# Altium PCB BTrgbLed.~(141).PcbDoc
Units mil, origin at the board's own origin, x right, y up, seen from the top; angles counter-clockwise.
Board outline 3886.28 x 3884.79 mil, 2 copper layers (Top Layer, Bottom Layer); 15 components, 12 nets, 66 pads, 7 vias.
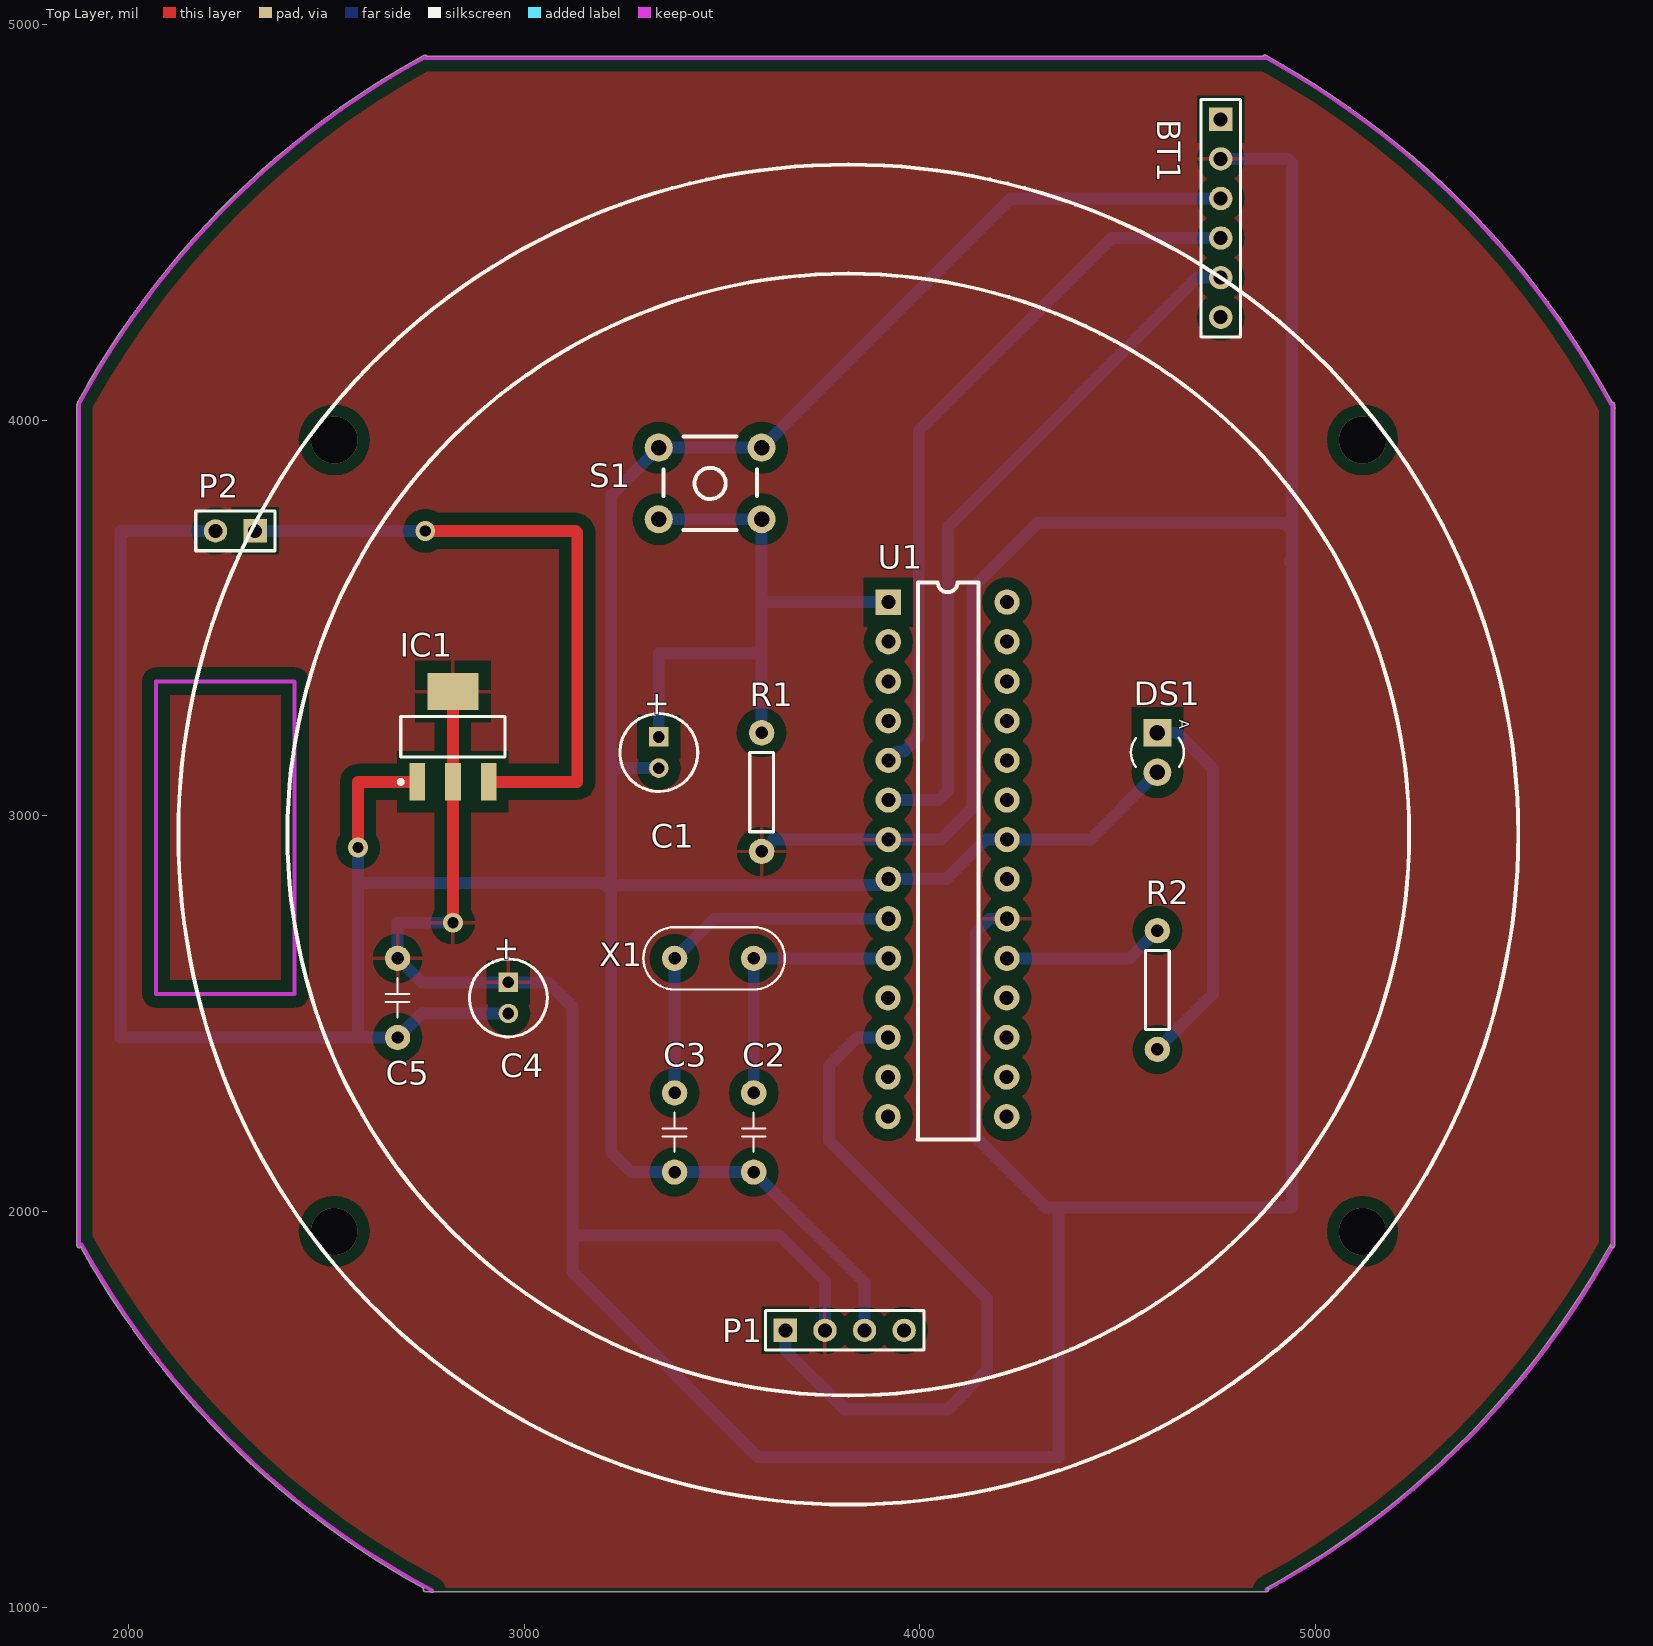
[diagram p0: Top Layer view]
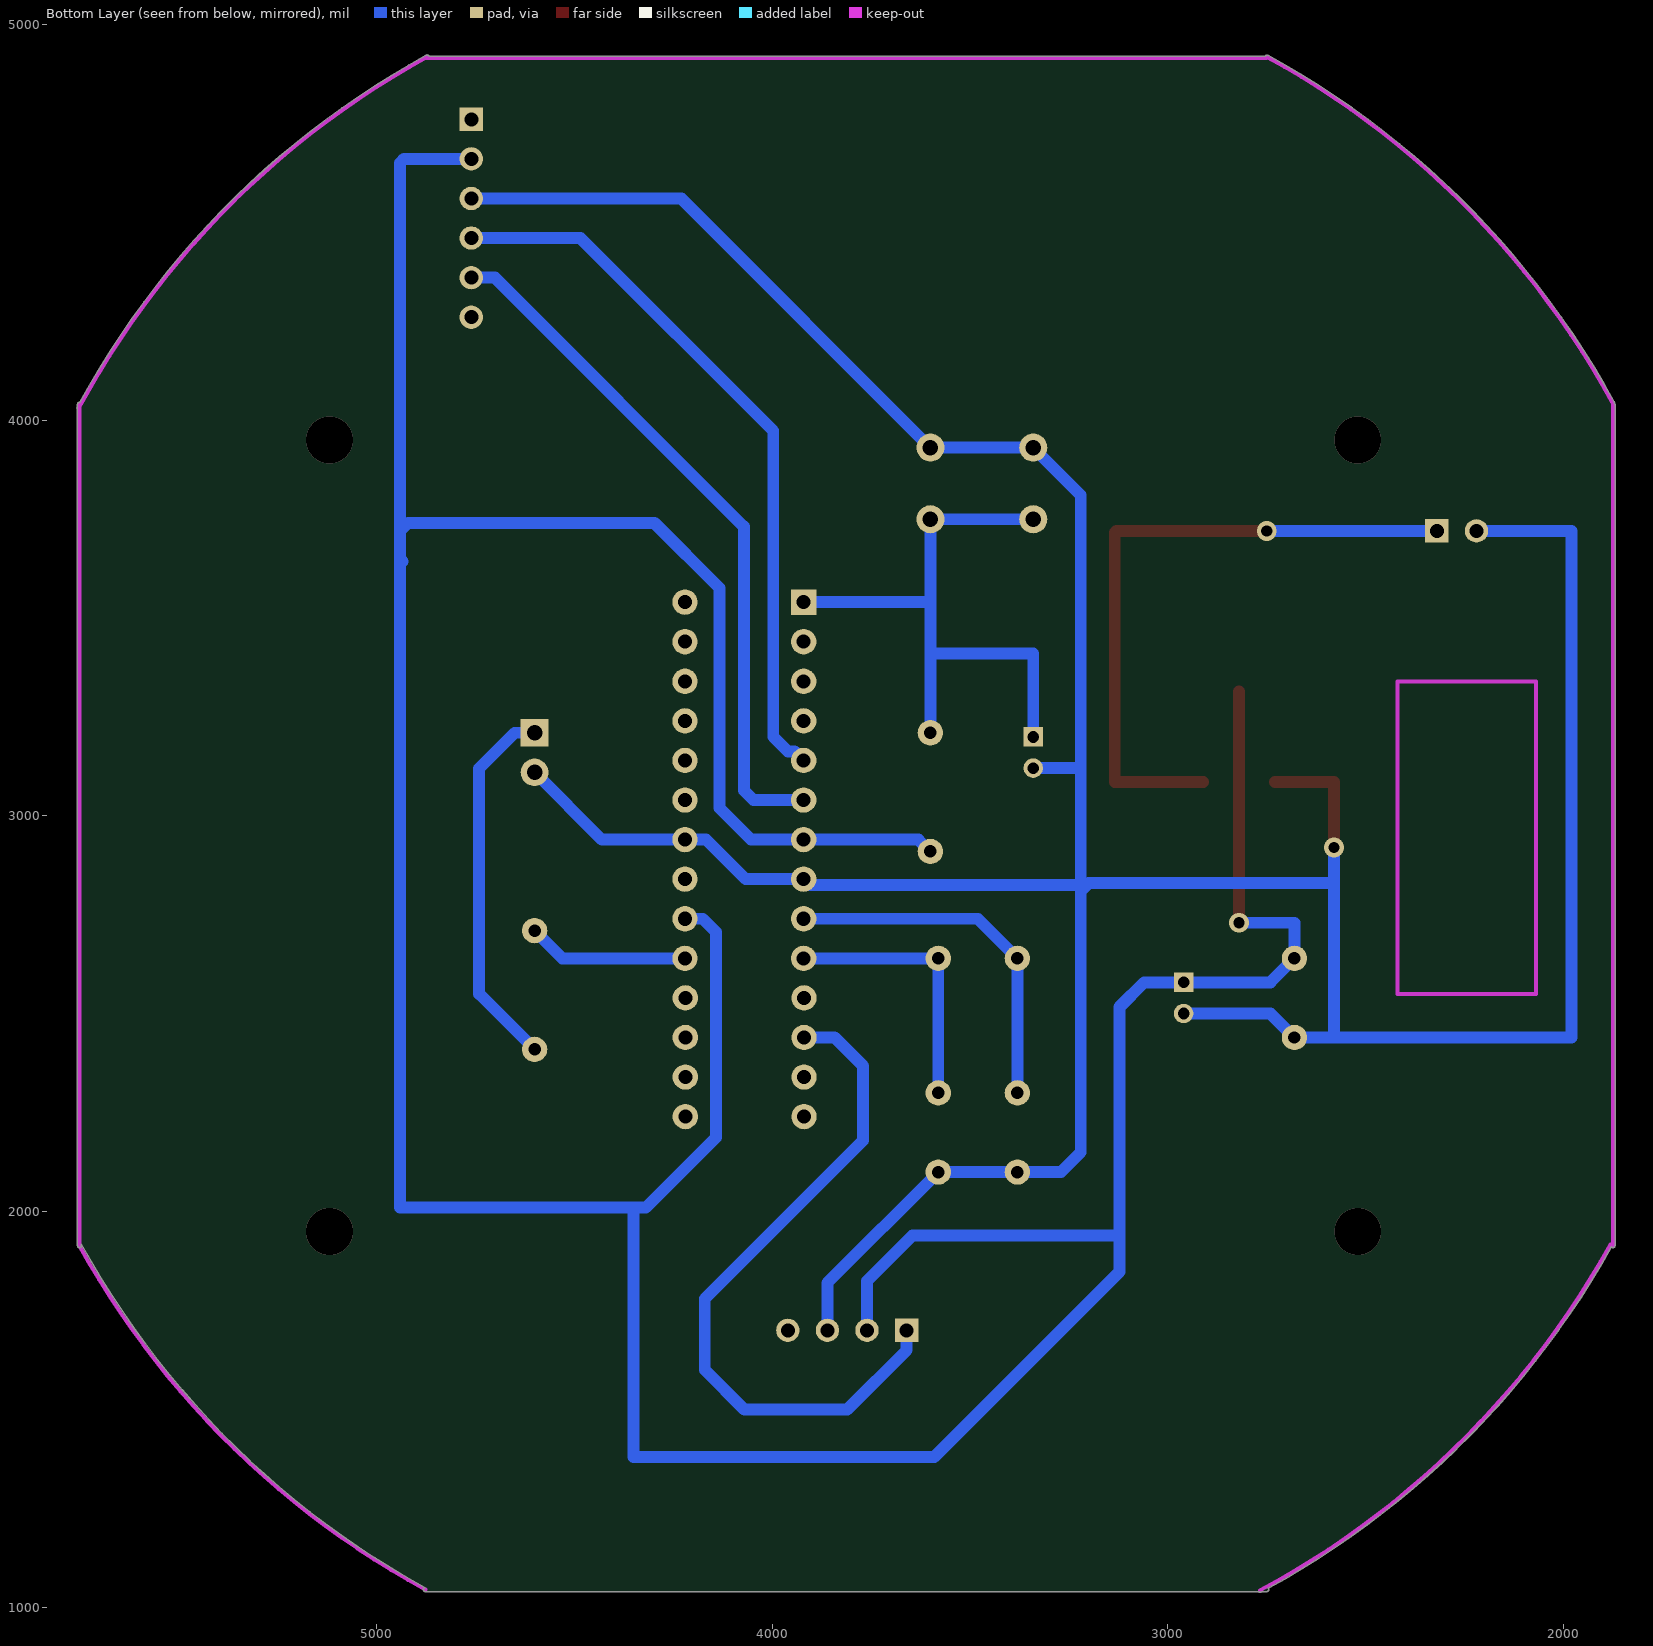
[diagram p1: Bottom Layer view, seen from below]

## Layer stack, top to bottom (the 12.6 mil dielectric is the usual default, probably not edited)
Top Layer: signal copper 1.4
Dielectric: dielectric 12.6, FR-4, Dk 4.8
Bottom Layer: signal copper 1.4

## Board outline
2750,1039.98 2761.53,1039.98 ccw(c3810.28,2985) 2764.5,1038.38 ccw(c2766.88,1042.8) 2771.03,1039.98 4875.98,1039.98 ccw(c4875.98,1045) 4881,1045 ccw(c4875.98,1045) 4877.16,1049.88 ccw(c3810.28,2985) 5744.74,1916.92 ccw(c5740.35,1919.34) 5744.98,1917.43 5744.98,1914.02 ccw(c5750,1914.02) 5755.02,1914.02 5755.02,4027.36 ccw(c5751.25,4030.67) 5756.26,4030.67 ccw(c5751.25,4030.67) 5755.66,4033.05 ccw(c3810.28,2985) 5755.02,4034.26 5755.02,4040 ccw(c5750,4040) 5749.21,4044.95 ccw(c3810.28,2985) 4873.82,4921.96 ccw(c4871.41,4917.56) 4867.03,4920.02 2752.96,4920.02 ccw(c2748.72,4917.33) 2746.3,4921.73 ccw(c3810.28,2985) 1872.41,4046.9 ccw(c1876.81,4044.49) 1871.83,4043.89 ccw(c1875,4040) 1869.98,4040 1869.98,1914.02 ccw(c1875,1914.02) 1879.06,1911.07 ccw(c3810.28,2985) 2746.23,1048.31 ccw(c2750,1045)

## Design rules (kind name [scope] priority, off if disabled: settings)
Clearance 舖銅安全間距 [All] p1: gap=30
Clearance [All] p2: gap=10
PolygonConnect [All] p1: connectstyle=Relief reliefconductorwidth=10 reliefentries=4 polygonreliefangle="90 Angle"
RoutingLayers [All] p1: top layer_v5=FALSE bottom layer_v5=TRUE
RoutingVias [All] p1: holewidth=28 width=50 viastyle="Through Hole" minholewidth=28 minwidth=50 maxholewidth=28 maxwidth=50
SilkscreenOverComponentPads [All] p1: minsilkscreentomaskgap=10
SolderMaskExpansion [All] p1: expansion=4
Width [All] p1: maxlimit=40 minlimit=20 preferedwidth=30
26 further rules are at their usual default settings.

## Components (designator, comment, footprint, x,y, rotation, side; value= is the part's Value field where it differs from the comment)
BT1 "Bluetooth" Bluetooth 4760,4760 r270 top
C1 "47uF" CAPPR2-5x6.8 3340,3160 r270 top
C2 "22pF" C200 3580,2200 r180 top
C3 "22pF" C200 3380,2200 r180 top
C4 "47uF" CAPPR2-5x6.8 2960,2540 r270 top
C5 "100pF" C200 2680,2540 r180 top
DS1 "TX-LED" LED-3mm_G 4600,3160 r270 top
IC1 "AM1117-5V" SOT-223 2820,3200 r90 top
P1 "環形LED燈" HDR1X4 3660,1700 r0 top
P2 "12V" HDR1X2 2320,3720 r180 top
R1 "10k" AXIAL-0.3 3600,3060 r90 top
R2 "220" AXIAL-0.3 4600,2560 r90 top
S1 "SW-PB" TACK6 3469.86,3840 r0 top
U1 "ATmega328" DIP-28 3920,3540 r270 top
X1 "16MHz" XTAL4-8 3480,2640 r0 top

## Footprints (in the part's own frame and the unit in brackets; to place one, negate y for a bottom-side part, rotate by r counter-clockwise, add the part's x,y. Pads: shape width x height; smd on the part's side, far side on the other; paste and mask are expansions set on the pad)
AXIAL-0.3 [mil] "0.3\" Resistor; 2 Leads"
  round 64 hole 31.5: 1(-150,0) 2(150,0)
  silkscreen extent -100,-30 100,30, body extent -161,-39 165,39, height 86
Bluetooth [mm]
  rect 1.5x1.5 hole 0.9: 1(0,0)
  round 1.5 hole 0.9: 2(2.54,0) 3(5.08,0) 4(7.62,0) 5(10.16,0) 6(12.7,0)
  silkscreen extent -1.27,-1.27 13.97,1.27, body extent -1.25,-1.3 13.97,1.28, height 11
C200 [mil] "塑膠電容器"
  round 64 hole 31.5: 1(0,100) 2(0,-100)
  silkscreen extent -30,-50 30,50, body extent -41,-136 39,135, height 354
CAPPR2-5x6.8 [mm] "Capacitor, Electrolytic, Radial; Body 5 x 6.8 mm (Dia.xH typ); Pin Spacing 2 mm (typ)"
  rect 1.25x1.25 hole 0.75: 1(-1,0)
  round 1.25 hole 0.75: 2(1,0)
  silkscreen extent -2.5,-2.5 2.5,2.5
DIP-28 [mil]
  rect 64x64 hole 35.43: 1(0,0)
  round 64 hole 35.43: 2(100,0) 3(200,0) 4(300,0) 5(400,0) 6(500,0) 7(600,0) 8(700,0) 9(800,0) 10(900,0) 11(1000,-0.79) 12(1100,-0.79) 13(1200,-0.79) 14(1300,-0.79) 15(1300,299.21) 16(1200,299.21) 17(1100,299.21) 18(1000,299.21) 19(900,300) 20(800,300) 21(700,300) 22(600,300) 23(500,300) 24(400,300) 25(300,300) 26(200,300) 27(100,300) 28(0,300)
  silkscreen extent -50,74 1358,228, body extent -53,-5 1358,304, height 209
HDR1X2 [mm] "Connector; Header; 2 Position"
  rect 1.5x1.5 hole 0.9: 1(0,0)
  round 1.5 hole 0.9: 2(2.54,0)
  silkscreen extent -1.27,-1.27 3.81,1.27
HDR1X4 [mm] "Connector; Header; 4 Position"
  rect 1.5x1.5 hole 0.9: 1(0,0)
  round 1.5 hole 0.9: 2(2.54,0) 3(5.08,0) 4(7.62,0)
  silkscreen extent -1.27,-1.27 8.89,1.27
LED-3mm_G [mil] "3mm LED_Green"
  rect 70x70 hole 39: 1(-50,0)
  round 70 hole 39: 2(50,0)
  silkscreen extent -38,-67 35,67, body extent -66,-68 67,66, height 181
SOT-223 [mm] "SOT223, 4-Leads, Body 6.7x7.3mm (max), Pitch 2.30mm, IPC Medium Density"
  rect 2.4x1 smd: 1(-2.9,2.3) 2(-2.9,0) 3(-2.9,-2.3)
  rect 2.4x3.3 smd: 2(2.9,0)
  silkscreen extent -3.02,-3.35 1.3,3.47, body extent -1.86,-3.35 1.86,3.35, height 1.8
TACK6 [mm]
  round 1.8 hole 1: 1(-3.3,2.3) 1(3.3,2.3) 2(-3.3,-2.3) 2(3.3,-2.3)
  silkscreen extent -3,-3 3,3, body extent -3,-3.01 3.08,3.04, height 8
XTAL4-8 [mil]
  round 64 hole 31.5: 1(-100,0) 2(100,0)
  silkscreen extent -179,-79 179,79, body extent -178,-80 192,79, height 157

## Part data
C1 C4: library part "Cap Pol1", "Polarized Capacitor (Radial)"
C2 C3 C5: library part Cap, "Capacitor"
DS1: library part LED, "Typical INFRARED GaAs LED"
IC1: library part AM1117
P1: library part "Header 4", "Header, 4-Pin"
P2: library part "Header 2", "Header, 2-Pin"
R1 R2: library part Res, "Resistor"
S1: "Switch"
U1: "Arduino"
X1: library part XTAL, "Crystal Oscillator"

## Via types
v1: diameter 118.11, hole 118.11, Top Layer to Bottom Layer, 4 vias
v2: diameter 50, hole 28, Top Layer to Bottom Layer, 3 vias

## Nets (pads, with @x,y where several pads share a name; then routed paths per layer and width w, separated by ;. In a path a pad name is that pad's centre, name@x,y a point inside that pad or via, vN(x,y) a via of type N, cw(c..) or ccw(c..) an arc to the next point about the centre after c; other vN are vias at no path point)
DI: P1.1 U1.12 | length 1776.3
  Bottom Layer w30: P1.1 3660,1650 3810,1500 4070,1500 4170,1600 4170,1780 3770,2180 3770,2368 3842,2440 U1.12
DO: P1.4
GND: BT1.3 C1.2 C2.1 C3.1 C4.2 C5.1 DS1.2 IC1.1 P1.3 P2.2 S1.1 U1.8 U1.22 | length 10003.4
  Top Layer w30: v2(2580,2920) 2580,3085.83 IC1.1
  Bottom Layer w30: P2.2 1980,3720 1980,2440 2580,2440 ; v2@2580,2915.83 2580,2830 ; C4.2 2740.63,2500.63 C5.1 2580,2440 ; 3220.63,3120.63 C1.2 ; 3225,2825 3920,2825 U1.8 4066.5,2840 4166.5,2940 U1.22 4430,2940 DS1.2 ; P1.3@3860,1690 3860,1820 C2.1 C3.1 3270,2100 3220,2150 3220,2810 ; BT1.3 4229.23,4560 3599.78,3930.55 3339.94,3930.55 3220,3810.61 3220,2810 ; 2580,2440 2580,2830 ; 2580,2830 3200,2830 3220,2810
NetC1_1: C1.1 R1.2 S1.2 U1.1 | length 1598.5
  Bottom Layer w30: S1.2@3339.94,3749.45 3599.78,3749.45 3599.78,3550 ; C1.1 3340,3410 3590,3410 3600,3400 ; R1.2 3600,3400 ; U1.1 3609.78,3540 3599.78,3550 ; 3599.78,3550 3599.78,3479.22 3600,3479 3600,3400
NetC2_2: C2.2 U1.10 X1.2 | length 680
  Bottom Layer w30: C2.2 X1.2 U1.10
NetC3_2: C3.2 U1.9 X1.1 | length 921.4
  Bottom Layer w30: C3.2 X1.1 3480,2740 U1.9
NetDS1_1: DS1.1 R2.1 | length 945.3
  Bottom Layer w30: R2.1 4740,2550 4740,3120 4650,3210 DS1.1
NetIC1_3: IC1.3 P2.1 | length 1669.5
  Top Layer w30: v2(2750,3720) 3130,3720 3134.17,3715.83 3134.17,3085.83 IC1.3
  Bottom Layer w30: P2.1 v2(2750,3720)
NetR2_2: R2.2 U1.19 | length 409
  Bottom Layer w30: U1.19 4530,2640 R2.2
RX: BT1.5 U1.6 | length 1777.2
  Bottom Layer w30: U1.6 4046.5,3040 4071,3064.5 4071,3731 4700,4360 BT1.5
TX: BT1.4 U1.5 | length 1839.6
  Bottom Layer w30: U1.5 3943,3163 3960,3163 3997,3200 3997,3973 4484,4460 BT1.4
VCC: BT1.2 C4.1 C5.2 IC1.2 P1.2 R1.1 U1.7 U1.20 | length 11163.4
  Top Layer w30: v2(2820,2730) 2820,3085.83 IC1.2@2820,3314.17
  Bottom Layer w30: v2(2820,2730) 2680,2730 C5.2 2740.63,2579.37 C4.1 3059.63,2579.37 3122,2517 3122,1940 ; R1.1 3630,2940 U1.7 4053,2940 4133,3020 4133,3576 4297,3740 4920,3740 4940,3720 ; P1.2 3760,1825 3645,1940 3122,1940 ; U1.20 4175,2740 4142,2707 4142,2187 4319,2010 4940,2010 4940,3650 ; 4350,2000 4350,1380 3590,1380 3122,1848 3122,1940 ; BT1.2 4930,4660 4940,4650 4940,3720 ; 4933,3643 4940,3650 ; 4940,3650 4940,3720
pads on no net: BT1.1 BT1.6 U1.2 U1.3 U1.4 U1.11 U1.13 U1.14 U1.15 U1.16 U1.17 U1.18 U1.21 U1.23 U1.24 U1.25 U1.26 U1.27 U1.28
copper on no net:
  other v1: 2520,1950 5118.43,1950 2520,3950 5118.43,3950

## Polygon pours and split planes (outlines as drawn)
VCC on Top Layer "Top Layer-No Net" (solid): 1873.98,1914.02 1875.81,1913.41 1875.82,1913.42 1882.55,1913.01 ccw(c3810.28,2985) 2748.16,1051.82 2750.17,1049 4873.26,1049 4875.23,1053.38 ccw(c3810.28,2985) 5741.24,1918.85 5741.24,1918.86 5741.29,1918.96 5748.98,1917.43 5748.98,1914.02 5751.02,1914.02 5751.02,4027.36 5752.01,4030 5752.02,4030.01 5752.26,4030.67 5752.14,4031.15 5751.49,4032.36 5751.02,4034.26 5751.02,4040 5749.85,4041 5749.84,4041 5745.7,4043.03 ccw(c3810.28,2985) 4871.9,4918.45 4871.89,4918.46 4870.52,4918.06 4867.03,4916.02 2752.96,4916.02 2749.58,4917.88 2749.57,4917.89 2748.23,4918.22 ccw(c3810.28,2985) 1875.92,4044.98 1875.91,4044.97 1875.8,4044.38 1875.8,4044.37 1875.83,4043.89 1874.36,4040.79 1874.35,4040.78 1873.98,4040

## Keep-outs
Keep-Out Layer:
  lines w10: 1875,1914.02 1875,4040 ; 1876.81,4044.49 cw(c3810.28,2985) 2748.72,4917.33 ; 1881.24,1917.47 ccw(c3810.28,2985) 2766.88,1042.8 ; 2750,4915 4875.98,4915 ; 4871.41,4917.56 cw(c3810.28,2985) 5751.25,4030.67 ; 4875.98,1045 ccw(c3820.75,2980.79) 5750.82,1915.13 ; 5750,1914.02 5750,4040 ; 2070,2550 2070,3340 2420,3340 2420,2550 2070,2550

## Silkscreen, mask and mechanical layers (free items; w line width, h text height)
Top Overlay:
  circle w10: c3818.9,2952.76 r1417.32
  circle w10: c3818.9,2952.76 r1692.91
